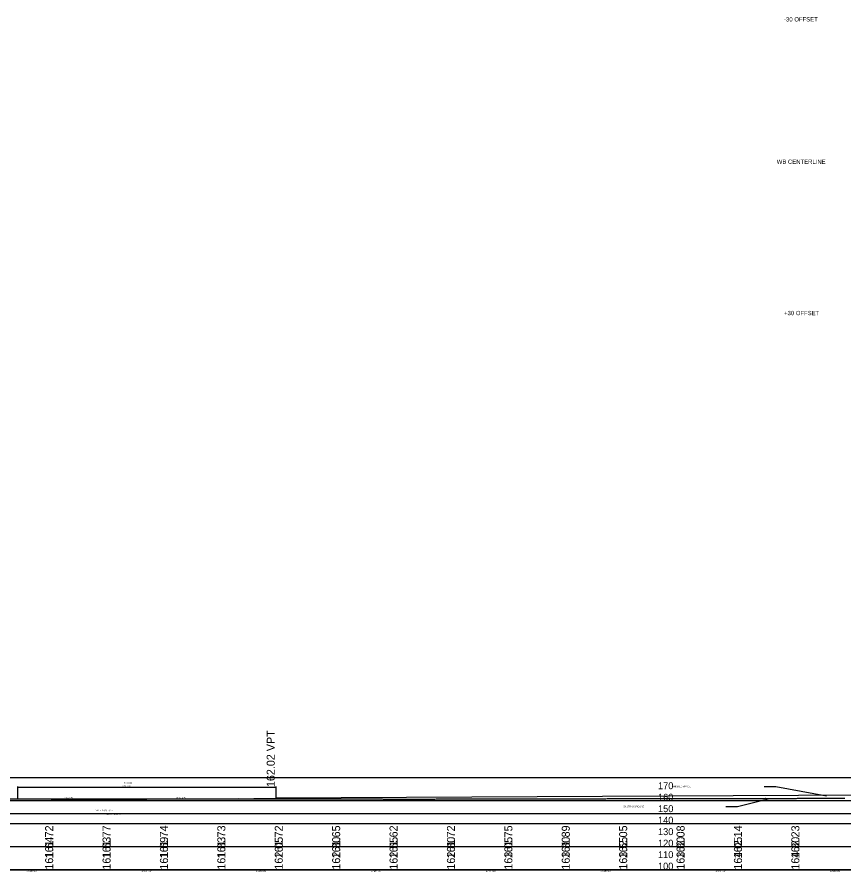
# Model space of a CAD drawing. Extents: x 2126510 to 2136144, y 865066 to 868066.
# Drawn here: x 2127736 to 2128457, y 866612 to 867356 of the extents above; entities that cross this region are included whole.
import ezdxf

# ---------------------------------------------------------------- set-up
doc = ezdxf.new("R2010")
doc.units = 0
for name, color, linetype in [('RD_EX_GuardRail', 7, 'Continuous'), ('RD_EX_H2O', 7, 'Continuous'), ('RD_EX_Misc', 7, 'Continuous')]:
    doc.layers.add(name, color=color, linetype=linetype)

msp = doc.modelspace()

# ---------------------------------------------------------------- linework, layer by layer
at = {"layer": 'RD_EX_GuardRail'}
for p, q in [((2131097.7, 866693.9), (2126517.45, 866693.9)), ((2128999.96, 866673.9), (2126517.45, 866673.9)), ((2131097.7, 866653.9), (2126517.45, 866653.9)), ((2131097.7, 866633.9), (2126517.45, 866633.9)), ((2131097.7, 866613.9), (2126517.45, 866613.9))]:
    msp.add_line(p, q, dxfattribs=at)
at = {"layer": 'RD_EX_H2O'}
for points in [[(2127736.19, 866675.58), (2127737.19, 866675.58)], [(2127937.19, 866675.57), (2127938.19, 866675.57), (2127939.19, 866675.57), (2127940.19, 866675.57), (2127941.19, 866675.58), (2127942.19, 866675.58), (2127943.19, 866675.58), (2127944.19, 866675.58), (2127945.19, 866675.58), (2127946.19, 866675.58), (2127947.19, 866675.58), (2127948.19, 866675.59), (2127949.19, 866675.59), (2127950.19, 866675.59), (2127951.19, 866675.59), (2127952.19, 866675.59), (2127953.19, 866675.59), (2127954.19, 866675.6), (2127955.19, 866675.6), (2127956.19, 866675.6), (2127957.19, 866675.6), (2127958.19, 866675.6), (2127959.19, 866675.6), (2127960.19, 866675.61), (2127961.19, 866675.61), (2127962.19, 866675.61), (2127963.19, 866675.61), (2127964.19, 866675.61), (2127965.19, 866675.62), (2127966.19, 866675.62), (2127967.19, 866675.62), (2127968.19, 866675.62), (2127969.19, 866675.62), (2127970.19, 866675.63), (2127971.19, 866675.63), (2127972.19, 866675.63), (2127973.19, 866675.63), (2127974.19, 866675.63), (2127975.19, 866675.63), (2127976.19, 866675.63), (2127977.19, 866675.63), (2127978.19, 866675.63), (2127979.19, 866675.63), (2127980.19, 866675.63), (2127981.19, 866675.62), (2127982.19, 866675.62), (2127983.19, 866675.62), (2127984.19, 866675.62), (2127985.19, 866675.62), (2127986.19, 866675.62), (2127987.19, 866675.62), (2127988.19, 866675.62), (2127989.19, 866675.62), (2127990.19, 866675.61), (2127991.19, 866675.61), (2127992.19, 866675.61), (2127993.19, 866675.61), (2127994.19, 866675.61), (2127995.19, 866675.6), (2127996.19, 866675.6), (2127997.19, 866675.6), (2127998.19, 866675.59), (2127999.19, 866675.59), (2128000.19, 866675.59), (2128001.19, 866675.59), (2128002.19, 866675.58), (2128003.19, 866675.58), (2128004.19, 866675.58), (2128005.19, 866675.57), (2128006.19, 866675.57), (2128007.19, 866675.57), (2128008.19, 866675.57), (2128009.19, 866675.56), (2128010.19, 866675.56), (2128011.19, 866675.56), (2128012.19, 866675.55), (2128013.19, 866675.55), (2128014.19, 866675.55), (2128015.19, 866675.55), (2128016.19, 866675.55), (2128017.19, 866675.55), (2128018.19, 866675.55), (2128019.19, 866675.56), (2128020.19, 866675.56), (2128021.19, 866675.56), (2128022.19, 866675.56), (2128023.19, 866675.56), (2128024.19, 866675.56), (2128025.19, 866675.56), (2128026.19, 866675.56), (2128027.19, 866675.56), (2128028.19, 866675.57), (2128029.19, 866675.57), (2128030.19, 866675.57), (2128031.19, 866675.57), (2128032.19, 866675.57), (2128033.19, 866675.57), (2128034.19, 866675.57), (2128035.19, 866675.57), (2128036.19, 866675.57), (2128037.19, 866675.57)], [(2128037.19, 866675.57), (2128038.19, 866675.57), (2128039.19, 866675.57), (2128040.19, 866675.56), (2128041.19, 866675.56), (2128042.19, 866675.56), (2128043.19, 866675.56), (2128044.19, 866675.56), (2128045.19, 866675.56), (2128046.19, 866675.56), (2128047.19, 866675.56), (2128048.19, 866675.55), (2128049.19, 866675.55), (2128050.19, 866675.55), (2128051.19, 866675.55), (2128052.19, 866675.55), (2128053.19, 866675.55), (2128054.19, 866675.55), (2128055.19, 866675.54), (2128056.19, 866675.54), (2128057.19, 866675.54), (2128058.19, 866675.54), (2128059.19, 866675.54), (2128060.19, 866675.54), (2128061.19, 866675.54), (2128062.19, 866675.53), (2128063.19, 866675.53), (2128064.19, 866675.53), (2128065.19, 866675.53), (2128066.19, 866675.52), (2128067.19, 866675.52), (2128068.19, 866675.52), (2128069.19, 866675.52), (2128070.19, 866675.52), (2128071.19, 866675.52), (2128072.19, 866675.52), (2128073.19, 866675.52), (2128074.19, 866675.52), (2128075.19, 866675.52), (2128076.19, 866675.52), (2128077.19, 866675.52), (2128078.19, 866675.52), (2128079.19, 866675.51), (2128080.19, 866675.51), (2128081.19, 866675.51), (2128082.19, 866675.51), (2128083.19, 866675.51), (2128084.19, 866675.51), (2128085.19, 866675.51), (2128086.19, 866675.5), (2128087.19, 866675.5), (2128088.19, 866675.5), (2128089.19, 866675.5), (2128090.19, 866675.5), (2128091.19, 866675.5), (2128092.19, 866675.5), (2128093.19, 866675.51), (2128094.19, 866675.51), (2128095.19, 866675.52), (2128096.19, 866675.52), (2128097.19, 866675.53), (2128098.19, 866675.53), (2128099.19, 866675.54), (2128100.19, 866675.54), (2128101.19, 866675.55), (2128102.19, 866675.55), (2128103.19, 866675.56), (2128104.19, 866675.56), (2128105.19, 866675.57), (2128106.19, 866675.57), (2128107.19, 866675.58), (2128108.19, 866675.58), (2128109.19, 866675.59), (2128110.19, 866675.6), (2128111.19, 866675.61), (2128112.19, 866675.61), (2128113.19, 866675.61), (2128114.19, 866675.61), (2128115.19, 866675.61), (2128116.19, 866675.62), (2128117.19, 866675.62), (2128118.19, 866675.62), (2128119.19, 866675.62), (2128120.19, 866675.62), (2128121.19, 866675.62), (2128122.19, 866675.63), (2128123.19, 866675.63), (2128124.19, 866675.63), (2128125.19, 866675.63), (2128126.19, 866675.63), (2128127.19, 866675.64), (2128128.19, 866675.64), (2128129.19, 866675.64), (2128130.19, 866675.64), (2128131.19, 866675.64), (2128132.19, 866675.64), (2128133.19, 866675.63), (2128134.19, 866675.63), (2128135.19, 866675.64), (2128136.19, 866675.64), (2128137.19, 866675.65)], [(2128137.19, 866675.65), (2128138.19, 866675.66), (2128139.19, 866675.66), (2128140.19, 866675.67), (2128141.19, 866675.67), (2128142.19, 866675.68), (2128143.19, 866675.69), (2128144.19, 866675.69), (2128145.19, 866675.7), (2128146.19, 866675.7), (2128147.19, 866675.71), (2128148.19, 866675.72), (2128149.19, 866675.72), (2128150.19, 866675.72), (2128151.19, 866675.72), (2128152.19, 866675.72), (2128153.19, 866675.72), (2128154.19, 866675.72), (2128155.19, 866675.71), (2128156.19, 866675.71), (2128157.19, 866675.7), (2128158.19, 866675.7), (2128159.19, 866675.69), (2128160.19, 866675.68), (2128161.19, 866675.68), (2128162.19, 866675.67), (2128163.19, 866675.67), (2128164.19, 866675.66), (2128165.19, 866675.66), (2128166.19, 866675.65), (2128167.19, 866675.65), (2128168.19, 866675.65), (2128169.19, 866675.66), (2128170.19, 866675.66), (2128171.19, 866675.67), (2128172.19, 866675.68), (2128173.19, 866675.68), (2128174.19, 866675.68), (2128175.19, 866675.69), (2128176.19, 866675.69), (2128177.19, 866675.69), (2128178.19, 866675.69), (2128179.19, 866675.7), (2128180.19, 866675.7), (2128181.19, 866675.7), (2128182.19, 866675.7), (2128183.19, 866675.71), (2128184.19, 866675.71), (2128185.19, 866675.71), (2128186.19, 866675.71), (2128187.19, 866675.72), (2128188.19, 866675.72), (2128189.19, 866675.72), (2128190.19, 866675.71), (2128191.19, 866675.71), (2128192.19, 866675.7), (2128193.19, 866675.7), (2128194.19, 866675.69), (2128195.19, 866675.69), (2128196.19, 866675.7), (2128197.19, 866675.71), (2128198.19, 866675.71), (2128199.19, 866675.72), (2128200.19, 866675.72), (2128201.19, 866675.73), (2128202.19, 866675.74), (2128203.19, 866675.74), (2128204.19, 866675.75), (2128205.19, 866675.76), (2128206.19, 866675.76), (2128207.19, 866675.77), (2128208.19, 866675.78), (2128209.19, 866675.78), (2128210.19, 866675.79), (2128211.19, 866675.79), (2128212.19, 866675.8), (2128213.19, 866675.8), (2128214.19, 866675.8), (2128215.19, 866675.8), (2128216.19, 866675.8), (2128217.19, 866675.8), (2128218.19, 866675.8), (2128219.19, 866675.8), (2128220.19, 866675.8), (2128221.19, 866675.8), (2128222.19, 866675.8), (2128223.19, 866675.8), (2128224.19, 866675.8), (2128225.19, 866675.8), (2128226.19, 866675.8), (2128227.19, 866675.8), (2128228.19, 866675.8), (2128229.19, 866675.8), (2128230.19, 866675.8), (2128231.19, 866675.8), (2128232.19, 866675.8), (2128233.19, 866675.8), (2128234.19, 866675.8), (2128235.19, 866675.8), (2128236.19, 866675.8), (2128237.19, 866675.8)], [(2128237.19, 866675.8), (2128238.19, 866675.8), (2128239.19, 866675.8), (2128240.19, 866675.8), (2128241.19, 866675.8), (2128242.19, 866675.8), (2128243.19, 866675.8), (2128244.19, 866675.8), (2128245.19, 866675.8), (2128246.19, 866675.81), (2128247.19, 866675.82), (2128248.19, 866675.83), (2128249.19, 866675.83), (2128250.19, 866675.84), (2128251.19, 866675.85), (2128252.19, 866675.86), (2128253.19, 866675.86), (2128254.19, 866675.87), (2128255.19, 866675.87), (2128256.19, 866675.88), (2128257.19, 866675.89), (2128258.19, 866675.89), (2128259.19, 866675.9), (2128260.19, 866675.91), (2128261.19, 866675.91), (2128262.19, 866675.92), (2128263.19, 866675.93), (2128264.19, 866675.93), (2128265.19, 866675.94), (2128266.19, 866675.95), (2128267.19, 866675.95), (2128268.19, 866675.95), (2128269.19, 866675.95), (2128270.19, 866675.95), (2128271.19, 866675.95), (2128272.19, 866675.95), (2128273.19, 866675.95), (2128274.19, 866675.95), (2128275.19, 866675.95), (2128276.19, 866675.95), (2128277.19, 866675.94), (2128278.19, 866675.94), (2128279.19, 866675.94), (2128280.19, 866675.94), (2128281.19, 866675.94), (2128282.19, 866675.94), (2128283.19, 866675.93), (2128284.19, 866675.93), (2128285.19, 866675.93), (2128286.19, 866675.93), (2128287.19, 866675.93), (2128288.19, 866675.92), (2128289.19, 866675.92), (2128290.19, 866675.92), (2128291.19, 866675.93), (2128292.19, 866675.93), (2128293.19, 866675.93), (2128294.19, 866675.93), (2128295.19, 866675.94), (2128296.19, 866675.94), (2128297.19, 866675.94), (2128298.19, 866675.94), (2128299.19, 866675.95), (2128300.19, 866675.95), (2128301.19, 866675.95), (2128302.19, 866675.95), (2128303.19, 866675.96), (2128304.19, 866675.96), (2128305.19, 866675.96), (2128306.19, 866675.97), (2128307.19, 866675.97), (2128308.19, 866675.97), (2128309.19, 866675.98), (2128310.19, 866675.98), (2128311.19, 866675.98), (2128312.19, 866675.98), (2128313.19, 866675.98), (2128314.19, 866675.98), (2128315.19, 866675.98), (2128316.19, 866675.98), (2128317.19, 866675.98), (2128318.19, 866675.98), (2128319.19, 866675.98), (2128320.19, 866675.98), (2128321.19, 866675.98), (2128322.19, 866675.98), (2128323.19, 866675.97), (2128324.19, 866675.97), (2128325.19, 866675.97), (2128326.19, 866675.97), (2128327.19, 866675.96), (2128328.19, 866675.96), (2128329.19, 866675.96), (2128330.19, 866675.96), (2128331.19, 866675.96), (2128332.19, 866675.96), (2128333.19, 866675.96), (2128334.19, 866675.96), (2128335.19, 866675.97), (2128336.19, 866675.97), (2128337.19, 866675.97)], [(2128337.19, 866675.97), (2128338.19, 866675.97), (2128339.19, 866675.98), (2128340.19, 866675.98), (2128341.19, 866675.98), (2128342.19, 866675.98), (2128343.19, 866675.99), (2128344.19, 866675.99), (2128345.19, 866675.99), (2128346.19, 866675.99), (2128347.19, 866675.99), (2128348.19, 866676), (2128349.19, 866676), (2128350.19, 866676), (2128351.19, 866676), (2128352.19, 866676), (2128353.19, 866676.01), (2128354.19, 866676.01), (2128355.19, 866676.01), (2128356.19, 866676.01), (2128357.19, 866676.01), (2128358.19, 866676.02), (2128359.19, 866676.02), (2128360.19, 866676.02), (2128361.19, 866676.02), (2128362.19, 866676.02), (2128363.19, 866676.03), (2128364.19, 866676.03), (2128365.19, 866676.03), (2128366.19, 866676.03), (2128367.19, 866676.03), (2128368.19, 866676.04), (2128369.19, 866676.04), (2128370.19, 866676.04), (2128371.19, 866676.05), (2128372.19, 866676.05), (2128373.19, 866676.05), (2128374.19, 866676.06), (2128375.19, 866676.06), (2128376.19, 866676.06), (2128377.19, 866676.07), (2128378.19, 866676.07), (2128379.19, 866676.08), (2128380.19, 866676.08), (2128381.19, 866676.09), (2128382.19, 866676.09), (2128383.19, 866676.1), (2128384.19, 866676.11), (2128385.19, 866676.11), (2128386.19, 866676.12), (2128387.19, 866676.12), (2128388.19, 866676.13), (2128389.19, 866676.12), (2128390.19, 866676.12), (2128391.19, 866676.12), (2128392.19, 866676.11), (2128393.19, 866676.11), (2128394.19, 866676.1), (2128395.19, 866676.1), (2128396.19, 866676.1), (2128397.19, 866676.09), (2128398.19, 866676.09), (2128399.19, 866676.09), (2128400.19, 866676.09), (2128401.19, 866676.09), (2128402.19, 866676.09), (2128403.19, 866676.09), (2128404.19, 866676.09), (2128405.19, 866676.1), (2128406.19, 866676.1), (2128407.19, 866676.1), (2128408.19, 866676.1), (2128409.19, 866676.1), (2128410.19, 866676.11), (2128411.19, 866676.11), (2128412.19, 866676.11), (2128413.19, 866676.12), (2128414.19, 866676.12), (2128415.19, 866676.12), (2128416.19, 866676.13), (2128417.19, 866676.13), (2128418.19, 866676.13), (2128419.19, 866676.14), (2128420.19, 866676.14), (2128421.19, 866676.14), (2128422.19, 866676.15), (2128423.19, 866676.15), (2128424.19, 866676.14), (2128425.19, 866676.14), (2128426.19, 866676.14), (2128427.19, 866676.14), (2128428.19, 866676.14), (2128429.19, 866676.14), (2128430.19, 866676.13), (2128431.19, 866676.13), (2128432.19, 866676.13), (2128433.19, 866676.13), (2128434.19, 866676.13), (2128435.19, 866676.13), (2128436.19, 866676.13), (2128437.19, 866676.13)], [(2128437.19, 866676.13), (2128438.19, 866676.14), (2128439.19, 866676.14), (2128440.19, 866676.14), (2128441.19, 866676.14), (2128442.19, 866676.14), (2128443.19, 866676.14), (2128444.19, 866676.14), (2128445.19, 866676.14), (2128446.19, 866676.15), (2128447.19, 866676.16), (2128448.19, 866676.17), (2128449.19, 866676.18), (2128450.19, 866676.18), (2128451.19, 866676.19), (2128452.19, 866676.2), (2128453.19, 866676.21), (2128454.19, 866676.22), (2128455.19, 866676.22), (2128456.19, 866676.22), (2128457.19, 866676.22)]]:
    msp.add_lwpolyline(points, dxfattribs=at)
at = {"layer": 'RD_EX_Misc'}
for p, q in [((2127736.73, 866686.42), (2127736.73, 866675.59)), ((2127736.73, 866685.92), (2127961.73, 866685.92)), ((2127961.73, 866686.42), (2127961.73, 866675.92)), ((2127961.73, 866676.62), (2129142.37, 866682.52)), ((2127722.94, 866675.62), (2127736.73, 866675.59)), ((2127769.23, 866675.53), (2127849.23, 866675.36)), ((2127929.2, 866675.76), (2127849.23, 866675.36)), ((2127368.72, 866613.9), (2131522.97, 866613.9))]:
    msp.add_line(p, q, dxfattribs=at)
for points in [[(2128387.18, 866686.52), (2128397.11, 866686.52), (2128441.39, 866678.32)], [(2127737.19, 866675.58), (2127738.19, 866675.58), (2127739.19, 866675.58), (2127740.19, 866675.58), (2127741.19, 866675.58), (2127742.19, 866675.58), (2127743.19, 866675.58), (2127744.19, 866675.57), (2127745.19, 866675.57), (2127746.19, 866675.57), (2127747.19, 866675.57), (2127748.19, 866675.57), (2127749.19, 866675.57), (2127750.19, 866675.57), (2127751.19, 866675.57), (2127752.19, 866675.57), (2127753.19, 866675.57), (2127754.19, 866675.57), (2127755.19, 866675.57), (2127756.19, 866675.57), (2127757.19, 866675.58), (2127758.19, 866675.58), (2127759.19, 866675.59), (2127760.19, 866675.59), (2127761.19, 866675.59), (2127762.19, 866675.6), (2127763.19, 866675.6), (2127764.19, 866675.6), (2127765.19, 866675.61), (2127766.19, 866675.61), (2127767.19, 866675.61), (2127768.19, 866675.62), (2127769.19, 866675.62), (2127770.19, 866675.62), (2127771.19, 866675.63), (2127772.19, 866675.63), (2127773.19, 866675.64), (2127774.19, 866675.64), (2127775.19, 866675.64), (2127776.19, 866675.64), (2127777.19, 866675.64), (2127778.19, 866675.64), (2127779.19, 866675.64), (2127780.19, 866675.64), (2127781.19, 866675.64), (2127782.19, 866675.64), (2127783.19, 866675.65), (2127784.19, 866675.65), (2127785.19, 866675.65), (2127786.19, 866675.65), (2127787.19, 866675.65), (2127788.19, 866675.65), (2127789.19, 866675.65), (2127790.19, 866675.65), (2127791.19, 866675.65), (2127792.19, 866675.65), (2127793.19, 866675.66), (2127794.19, 866675.66), (2127795.19, 866675.66), (2127796.19, 866675.66), (2127797.19, 866675.66), (2127798.19, 866675.66), (2127799.19, 866675.66), (2127800.19, 866675.66), (2127801.19, 866675.66), (2127802.19, 866675.66), (2127803.19, 866675.66), (2127804.19, 866675.66), (2127805.19, 866675.66), (2127806.19, 866675.66), (2127807.19, 866675.66), (2127808.19, 866675.67), (2127809.19, 866675.67), (2127810.19, 866675.67), (2127811.19, 866675.67), (2127812.19, 866675.67), (2127813.19, 866675.67), (2127814.19, 866675.67), (2127815.19, 866675.67), (2127816.19, 866675.67), (2127817.19, 866675.67), (2127818.19, 866675.67), (2127819.19, 866675.67), (2127820.19, 866675.67), (2127821.19, 866675.67), (2127822.19, 866675.67), (2127823.19, 866675.67), (2127824.19, 866675.67), (2127825.19, 866675.67), (2127826.19, 866675.67), (2127827.19, 866675.67), (2127828.19, 866675.67), (2127829.19, 866675.67), (2127830.19, 866675.67), (2127831.19, 866675.67), (2127832.19, 866675.67), (2127833.19, 866675.67), (2127834.19, 866675.67), (2127835.19, 866675.67), (2127836.19, 866675.67), (2127837.19, 866675.66)], [(2127837.19, 866675.66), (2127838.19, 866675.66), (2127839.19, 866675.66), (2127840.19, 866675.66), (2127841.19, 866675.66), (2127842.19, 866675.65), (2127843.19, 866675.65), (2127844.19, 866675.65), (2127845.19, 866675.65), (2127846.19, 866675.65), (2127847.19, 866675.64), (2127848.19, 866675.64), (2127849.19, 866675.64), (2127850.19, 866675.64), (2127851.19, 866675.64), (2127852.19, 866675.64), (2127853.19, 866675.63), (2127854.19, 866675.63), (2127855.19, 866675.63), (2127856.19, 866675.63), (2127857.19, 866675.63), (2127858.19, 866675.63), (2127859.19, 866675.63), (2127860.19, 866675.64), (2127861.19, 866675.64), (2127862.19, 866675.64), (2127863.19, 866675.64), (2127864.19, 866675.64), (2127865.19, 866675.64), (2127866.19, 866675.64), (2127867.19, 866675.64), (2127868.19, 866675.64), (2127869.19, 866675.64), (2127870.19, 866675.64), (2127871.19, 866675.65), (2127872.19, 866675.65), (2127873.19, 866675.65), (2127874.19, 866675.65), (2127875.19, 866675.65), (2127876.19, 866675.65), (2127877.19, 866675.65), (2127878.19, 866675.65), (2127879.19, 866675.65), (2127880.19, 866675.65), (2127881.19, 866675.66), (2127882.19, 866675.66), (2127883.19, 866675.66), (2127884.19, 866675.66), (2127885.19, 866675.66), (2127886.19, 866675.66), (2127887.19, 866675.67), (2127888.19, 866675.67), (2127889.19, 866675.67), (2127890.19, 866675.67), (2127891.19, 866675.67), (2127892.19, 866675.67), (2127893.19, 866675.68), (2127894.19, 866675.68), (2127895.19, 866675.68), (2127896.19, 866675.68), (2127897.19, 866675.68), (2127898.19, 866675.68), (2127899.19, 866675.68), (2127900.19, 866675.67), (2127901.19, 866675.67), (2127902.19, 866675.67), (2127903.19, 866675.67), (2127904.19, 866675.67), (2127905.19, 866675.67), (2127906.19, 866675.67), (2127907.19, 866675.67), (2127908.19, 866675.66), (2127909.19, 866675.66), (2127910.19, 866675.66), (2127911.19, 866675.66), (2127912.19, 866675.66), (2127913.19, 866675.66), (2127914.19, 866675.65), (2127915.19, 866675.65), (2127916.19, 866675.64), (2127917.19, 866675.64), (2127918.19, 866675.63), (2127919.19, 866675.63), (2127920.19, 866675.62), (2127921.19, 866675.62), (2127922.19, 866675.61), (2127923.19, 866675.61), (2127924.19, 866675.6), (2127925.19, 866675.6), (2127926.19, 866675.59), (2127927.19, 866675.59), (2127928.19, 866675.58), (2127929.19, 866675.58), (2127930.19, 866675.57), (2127931.19, 866675.57), (2127932.19, 866675.56), (2127933.19, 866675.56), (2127934.19, 866675.57), (2127935.19, 866675.57), (2127936.19, 866675.57), (2127937.19, 866675.57)], [(2128353.72, 866669.04), (2128363.91, 866669.04), (2128391.69, 866676.11)], [(2127275.85, 866613.9), (2127275.85, 866662.9), (2131989.68, 866662.9)]]:
    msp.add_lwpolyline(points, dxfattribs=at)
msp.add_spline([(2127736.73, 866675.59), (2127741.23, 866675.58), (2127745.73, 866675.58), (2127750.23, 866675.57), (2127754.73, 866675.56), (2127759.23, 866675.56), (2127763.73, 866675.55), (2127768.23, 866675.54), (2127772.73, 866675.54), (2127777.23, 866675.54), (2127781.73, 866675.53), (2127786.23, 866675.53), (2127790.73, 866675.53), (2127795.23, 866675.53), (2127799.73, 866675.53), (2127804.23, 866675.52), (2127808.73, 866675.53), (2127813.23, 866675.53), (2127817.73, 866675.53), (2127822.23, 866675.53), (2127826.73, 866675.53), (2127831.23, 866675.54), (2127835.73, 866675.54), (2127840.23, 866675.55), (2127844.73, 866675.55), (2127849.23, 866675.56), (2127853.73, 866675.57), (2127858.23, 866675.57), (2127862.73, 866675.58), (2127867.23, 866675.59), (2127871.73, 866675.6), (2127876.23, 866675.61), (2127880.73, 866675.62), (2127885.23, 866675.63), (2127889.73, 866675.64), (2127894.23, 866675.66), (2127898.73, 866675.67), (2127903.23, 866675.68), (2127907.73, 866675.7), (2127912.23, 866675.71), (2127916.73, 866675.73), (2127921.23, 866675.75), (2127925.73, 866675.76), (2127930.23, 866675.78), (2127934.73, 866675.8), (2127939.23, 866675.82), (2127943.73, 866675.84), (2127948.23, 866675.86), (2127952.73, 866675.88), (2127957.23, 866675.9), (2127961.73, 866675.92)], degree=3, dxfattribs=at)

# ---------------------------------------------------------------- texts
for s, height, rotation, p in [('-30 OFFSET', 3.75, 0.00901, (2128404.38, 867352.39)), ('WB CENTERLINE ', 3.75, 0.00901, (2128398, 867228.44)), ('+30 OFFSET', 3.75, 0.00901, (2128404.4, 867096.71)), ('162.02 VPT', 7, 90, (2127960.73, 866685.92)), ('(-) 0.21%', 1.402, 359.88053, (2127776.93, 866675.91)), ('(+) 0.50%', 1.41, 0.28648, (2127874.84, 866675.89)), ('161.72', 7, 90, (2127767.72, 866623.9)), ('161.77', 7, 90, (2127817.72, 866623.9)), ('161.74', 7, 90, (2127867.72, 866623.9)), ('161.73', 7, 90, (2127917.72, 866623.9)), ('161.72', 7, 90, (2127967.72, 866623.9)), ('161.65', 7, 90, (2128017.72, 866623.9)), ('161.62', 7, 90, (2128067.72, 866623.9)), ('161.72', 7, 90, (2128117.72, 866623.9)), ('161.75', 7, 90, (2128167.72, 866623.9)), ('161.89', 7, 90, (2128217.72, 866623.9)), ('162.05', 7, 90, (2128267.72, 866623.9)), ('162.08', 7, 90, (2128317.72, 866623.9)), ('162.14', 7, 90, (2128367.72, 866623.9)), ('162.23', 7, 90, (2128417.72, 866623.9)), ('161.64', 7, 90, (2127767.72, 866614.05)), ('161.63', 7, 90, (2127817.72, 866614.05)), ('161.69', 7, 90, (2127867.72, 866614.05)), ('161.83', 7, 90, (2127917.72, 866614.05)), ('162.05', 7, 90, (2127967.72, 866614.05)), ('162.30', 7, 90, (2128017.72, 866614.05)), ('162.55', 7, 90, (2128067.72, 866614.05)), ('162.80', 7, 90, (2128117.72, 866614.05)), ('163.05', 7, 90, (2128167.72, 866614.05)), ('163.30', 7, 90, (2128217.72, 866614.05)), ('163.55', 7, 90, (2128267.72, 866614.05)), ('163.80', 7, 90, (2128317.72, 866614.05)), ('164.05', 7, 90, (2128367.72, 866614.05)), ('164.30', 7, 90, (2128417.72, 866614.05))]:
    msp.add_text(s, height=height, rotation=rotation, dxfattribs=at).set_placement(p)
for s, height, p in [('K = 318', 1.4, (2127829.67, 866688.97)), ('170', 6, (2128294.57, 866684.1)), ("225' V.C.", 1.4, (2127827.97, 866686.17)), ('FINISHED GRADE', 1.4, (2128306.71, 866685.82)), ('160', 6, (2128294.57, 866674.1)), ('VPI = 1793+80.51', 1.4, (2127804.75, 866664.96)), ('EXISTING GROUND', 1.4, (2128264.41, 866668.34)), ('150', 6, (2128294.57, 866664.1)), ('Elev. = 161.46', 1.4, (2127814.17, 866661.96)), ('140', 6, (2128294.57, 866654.1)), ('130', 6, (2128294.57, 866644.1)), ('120', 6, (2128294.57, 866634.1)), ('110', 6, (2128294.57, 866624.1)), ('100', 6, (2128294.57, 866614.1)), ('1793+00', 1.6, (2127744.51, 866612.1)), ('1794+00', 1.6, (2127844.51, 866612.1)), ('1795+00', 1.6, (2127944.51, 866612.1)), ('1796+00', 1.6, (2128044.51, 866612.1)), ('1797+00', 1.6, (2128144.51, 866612.1)), ('1798+00', 1.6, (2128244.51, 866612.1)), ('1799+00', 1.6, (2128344.51, 866612.1)), ('1800+00', 1.6, (2128444.51, 866612.1))]:
    msp.add_text(s, height=height, dxfattribs=at).set_placement(p)

doc.saveas('drawing.dxf')
